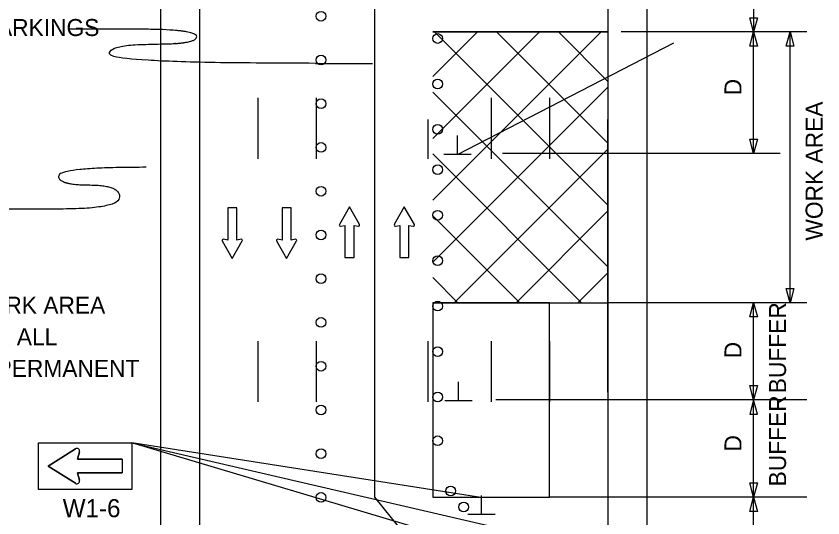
# Model space of a CAD drawing. Extents: x 16544 to 19504, y 5662 to 6922.
# Drawn here: x 16864 to 17195.9, y 6268.5 to 6474.9 of the extents above; entities that cross this region are included whole.
import ezdxf

# ---------------------------------------------------------------- set-up
doc = ezdxf.new("R2010")
doc.units = 0
for name, color, linetype in [('ALI_LEGAL_EX', 7, 'Continuous'), ('MT_SCRATCH_LEVEL_A', 7, 'Continuous'), ('MT_SCRATCH_LEVEL_E', 7, 'Continuous'), ('PAVT_EDGE_EX', 7, 'Continuous'), ('TRAFFIC_SIGNS_PR', 7, 'Continuous'), ('TYPICAL_TEXT_DIMEN_PR', 7, 'Continuous')]:
    doc.layers.add(name, color=color, linetype=linetype)

msp = doc.modelspace()

# ---------------------------------------------------------------- linework, layer by layer
at = {"layer": 'ALI_LEGAL_EX'}
for points in [[(16963.46, 6441.23), (16963.46, 6416.23)], [(16987.46, 6441.23), (16987.46, 6416.23)], [(16987.46, 6441.23), (16987.46, 6416.23)], [(17059.46, 6441.23), (17059.46, 6416.23)], [(17083.46, 6441.23), (17083.46, 6416.23)], [(17033.46, 6432.41), (17033.46, 6416.23)], [(17033.46, 6432.41), (17033.46, 6416.23)], [(17059.46, 6432.41), (17059.46, 6416.23)], [(16963.46, 6341.23), (16963.46, 6316.23)], [(16987.46, 6341.23), (16987.46, 6316.23)], [(16987.46, 6341.23), (16987.46, 6316.23)], [(17033.46, 6341.23), (17033.46, 6316.23)], [(17033.46, 6341.23), (17033.46, 6316.23)], [(17059.46, 6341.23), (17059.46, 6316.23)], [(17059.46, 6341.23), (17059.46, 6316.23)], [(17083.46, 6341.23), (17083.46, 6316.23)]]:
    msp.add_lwpolyline(points, dxfattribs=at)
at = {"layer": 'MT_SCRATCH_LEVEL_A'}
for p, q in [((17035.46, 6468.41), (17107.46, 6468.41)), ((17035.46, 6468.41), (17107.46, 6468.41)), ((17107.46, 6468.41), (17035.46, 6468.41)), ((17035.46, 6399.15), (17104.72, 6468.41)), ((17035.46, 6450.04), (17053.83, 6468.41)), ((17035.46, 6424.59), (17079.28, 6468.41)), ((17107.46, 6397.15), (17036.2, 6468.41)), ((17107.46, 6422.59), (17061.64, 6468.41)), ((17107.46, 6448.04), (17087.1, 6468.41)), ((17035.46, 6373.69), (17107.46, 6445.69)), ((17107.46, 6371.69), (17035.46, 6443.69)), ((17107.46, 6432.41), (17107.46, 6320.18)), ((17107.46, 6348.23), (17107.46, 6432.41)), ((17044.23, 6357.01), (17107.46, 6420.23)), ((17096.69, 6357.01), (17035.46, 6418.24)), ((17069.69, 6357.01), (17107.46, 6394.78)), ((17071.23, 6357.01), (17035.46, 6392.78)), ((17045.78, 6357.01), (17035.46, 6367.33)), ((17095.15, 6357.01), (17107.46, 6369.32)), ((17035.46, 6357.01), (17107.46, 6357.01)), ((17107.46, 6320.18), (17107.46, 6348.23))]:
    msp.add_line(p, q, dxfattribs=at)
at = {"layer": 'MT_SCRATCH_LEVEL_E'}
for p, q in [((16954.79, 6396.02), (16951.05, 6396.02)), ((16951.05, 6396.02), (16951.05, 6382.76)), ((16954.79, 6396.02), (16951.05, 6396.02)), ((16951.05, 6396.02), (16951.05, 6382.76)), ((16954.79, 6382.76), (16954.79, 6396.02)), ((16954.79, 6382.76), (16954.79, 6396.02)), ((16977.13, 6396.02), (16973.39, 6396.02)), ((16973.39, 6396.02), (16973.39, 6382.76)), ((16977.13, 6396.02), (16973.39, 6396.02)), ((16973.39, 6396.02), (16973.39, 6382.76)), ((16977.13, 6382.76), (16977.13, 6396.02)), ((16977.13, 6382.76), (16977.13, 6396.02)), ((17001.14, 6396.4), (16997.03, 6389.16)), ((17001.14, 6396.4), (16997.03, 6389.16)), ((17001.14, 6396.4), (16997.03, 6389.16)), ((17001.14, 6396.4), (16997.03, 6389.16)), ((17005.29, 6389.16), (17001.14, 6396.4)), ((17005.29, 6389.16), (17001.14, 6396.4)), ((17005.29, 6389.16), (17001.14, 6396.4)), ((17005.29, 6389.16), (17001.14, 6396.4)), ((17023.72, 6396.4), (17019.61, 6389.16)), ((17023.72, 6396.4), (17019.61, 6389.16)), ((17027.87, 6389.16), (17023.72, 6396.4)), ((17027.87, 6389.16), (17023.72, 6396.4)), ((16997.51, 6388.47), (16999.29, 6388.79)), ((16997.51, 6388.47), (16999.29, 6388.79)), ((16997.51, 6388.47), (16999.29, 6388.79)), ((16997.51, 6388.47), (16999.29, 6388.79)), ((16999.29, 6388.79), (16999.29, 6375.53)), ((16999.29, 6388.79), (16999.29, 6375.53)), ((16999.29, 6388.79), (16999.29, 6375.53)), ((16999.29, 6388.79), (16999.29, 6375.53)), ((17003.03, 6375.53), (17003.03, 6388.79)), ((17003.03, 6388.79), (17004.81, 6388.47)), ((17003.03, 6375.53), (17003.03, 6388.79)), ((17003.03, 6388.79), (17004.81, 6388.47)), ((17003.03, 6375.53), (17003.03, 6388.79)), ((17003.03, 6388.79), (17004.81, 6388.47)), ((17003.03, 6375.53), (17003.03, 6388.79)), ((17003.03, 6388.79), (17004.81, 6388.47)), ((17020.09, 6388.47), (17021.87, 6388.79)), ((17020.09, 6388.47), (17021.87, 6388.79)), ((17021.87, 6388.79), (17021.87, 6375.53)), ((17021.87, 6388.79), (17021.87, 6375.53)), ((17025.61, 6375.53), (17025.61, 6388.79)), ((17025.61, 6388.79), (17027.39, 6388.47)), ((17025.61, 6375.53), (17025.61, 6388.79)), ((17025.61, 6388.79), (17027.39, 6388.47)), ((16948.79, 6382.39), (16952.94, 6375.15)), ((16948.79, 6382.39), (16952.94, 6375.15)), ((16951.05, 6382.76), (16949.27, 6383.08)), ((16951.05, 6382.76), (16949.27, 6383.08)), ((16952.94, 6375.15), (16957.05, 6382.39)), ((16952.94, 6375.15), (16957.05, 6382.39)), ((16956.57, 6383.08), (16954.79, 6382.76)), ((16956.57, 6383.08), (16954.79, 6382.76)), ((16971.13, 6382.39), (16975.28, 6375.15)), ((16971.13, 6382.39), (16975.28, 6375.15)), ((16973.39, 6382.76), (16971.61, 6383.08)), ((16973.39, 6382.76), (16971.61, 6383.08)), ((16975.28, 6375.15), (16979.39, 6382.39)), ((16975.28, 6375.15), (16979.39, 6382.39)), ((16978.91, 6383.08), (16977.13, 6382.76)), ((16978.91, 6383.08), (16977.13, 6382.76)), ((16999.29, 6375.53), (17003.03, 6375.53)), ((16999.29, 6375.53), (17003.03, 6375.53)), ((16999.29, 6375.53), (17003.03, 6375.53)), ((16999.29, 6375.53), (17003.03, 6375.53)), ((17021.87, 6375.53), (17025.61, 6375.53)), ((17021.87, 6375.53), (17025.61, 6375.53))]:
    msp.add_line(p, q, dxfattribs=at)
for centre, start, end in [((16997.44, 6388.93), 150.4248, 279.9638), ((16997.44, 6388.93), 150.4248, 279.9638), ((16997.44, 6388.93), 150.4248, 279.9638), ((16997.44, 6388.93), 150.4248, 279.9638), ((17004.88, 6388.93), 260.0362, 29.7731), ((17004.88, 6388.93), 260.0362, 29.7731), ((17004.88, 6388.93), 260.0362, 29.7731), ((17004.88, 6388.93), 260.0362, 29.7731), ((17020.02, 6388.93), 150.4248, 279.9638), ((17020.02, 6388.93), 150.4248, 279.9638), ((17027.46, 6388.93), 260.0362, 29.7731), ((17027.46, 6388.93), 260.0362, 29.7731), ((16949.2, 6382.62), 80.0362, 209.7731), ((16949.2, 6382.62), 80.0362, 209.7731), ((16956.64, 6382.62), 330.4248, 99.9638), ((16956.64, 6382.62), 330.4248, 99.9638), ((16971.54, 6382.62), 80.0362, 209.7731), ((16971.54, 6382.62), 80.0362, 209.7731), ((16978.98, 6382.62), 330.4248, 99.9638), ((16978.98, 6382.62), 330.4248, 99.9638)]:
    msp.add_arc(centre, 0.463, start, end, dxfattribs=at)
at = {"layer": 'PAVT_EDGE_EX'}
for p, q in [((16923.46, 6880.02), (16923.46, 6074.05)), ((16939.46, 6880.02), (16939.46, 6074.05)), ((17107.46, 6880.02), (17107.46, 6074.05)), ((17123.46, 6880.02), (17123.46, 6074.05)), ((17011.46, 6478.73), (17011.46, 6277.01)), ((17011.46, 6277.01), (17059.46, 6217.4))]:
    msp.add_line(p, q, dxfattribs=at)
msp.add_lwpolyline([(17083.46, 6357.01), (17035.46, 6357.01), (17035.46, 6277.01), (17083.46, 6277.01)], close=True, dxfattribs=at)
at = {"layer": 'TRAFFIC_SIGNS_PR'}
for p, q in [((16888.38, 6296.88), (16877.22, 6289.78)), ((16889.23, 6292.58), (16890.06, 6295.64)), ((16907.62, 6292.58), (16889.23, 6292.58)), ((16907.62, 6292.58), (16907.62, 6286.98)), ((16877.22, 6289.78), (16888.38, 6282.68)), ((16890.06, 6283.92), (16889.23, 6286.98)), ((16889.23, 6286.98), (16907.62, 6286.98))]:
    msp.add_line(p, q, dxfattribs=at)
msp.add_lwpolyline([(16911.62, 6280.18), (16873.22, 6280.18), (16873.22, 6299.38), (16911.62, 6299.38)], close=True, dxfattribs=at)
for points in [[(16888.38, 6282.68), (16877.22, 6289.78), (16888.38, 6296.88)], [(16890.06, 6295.64), (16889.23, 6292.58), (16907.62, 6292.58), (16907.62, 6286.98), (16889.23, 6286.98), (16890.06, 6283.92)]]:
    msp.add_lwpolyline(points, dxfattribs=at)
for centre in [(16989.46, 6474.87), (17037.46, 6465.7), (16989.46, 6456.87), (17037.46, 6447), (16989.46, 6438.87), (17037.46, 6428.29), (16989.46, 6420.87), (17037.46, 6411.7), (16989.46, 6402.87), (17037.46, 6393), (16989.46, 6384.87), (17037.46, 6374.29), (16989.46, 6366.87), (17037.46, 6355.59), (16989.46, 6348.87), (17037.46, 6336.88), (16989.46, 6330.87), (17037.46, 6318.18), (16989.46, 6312.87), (17037.46, 6300.18), (16989.46, 6294.87), (17042.79, 6279.55), (16989.46, 6276.87), (17048.13, 6272.93)]:
    msp.add_circle(centre, 2, dxfattribs=at)
for centre, start, end in [((16888.99, 6295.94), 344.6731, 122.4696), ((16888.99, 6295.94), 344.6731, 122.4696), ((16888.99, 6283.62), 237.5304, 15.3269), ((16888.99, 6283.62), 237.5304, 15.3269)]:
    msp.add_arc(centre, 1.12, start, end, dxfattribs=at)
at = {"layer": 'TYPICAL_TEXT_DIMEN_PR'}
for p, q in [((17167.46, 6492.87), (17167.46, 6468.41)), ((17167.46, 6468.41), (17165.89, 6474.27)), ((17165.89, 6474.27), (17167.46, 6474.27)), ((17167.46, 6474.27), (17169.03, 6474.27)), ((17169.03, 6474.27), (17167.46, 6468.41)), ((17189.31, 6468.41), (17112.96, 6468.41)), ((17165.89, 6462.55), (17167.46, 6468.41)), ((17167.46, 6418.41), (17167.46, 6468.41)), ((17167.46, 6468.41), (17169.03, 6462.55)), ((17180.89, 6462.55), (17182.46, 6468.41)), ((17182.46, 6357.01), (17182.46, 6468.41)), ((17182.46, 6468.41), (17184.03, 6462.55)), ((17045.66, 6418.04), (17134.66, 6463.9)), ((17167.46, 6462.55), (17165.89, 6462.55)), ((17169.03, 6462.55), (17167.46, 6462.55)), ((17182.46, 6462.55), (17180.89, 6462.55)), ((17184.03, 6462.55), (17182.46, 6462.55)), ((16987.12, 6455.48), (17010.62, 6455.48)), ((17045.66, 6418.04), (17045.66, 6425.83)), ((17167.46, 6418.41), (17165.89, 6424.27)), ((17165.89, 6424.27), (17167.46, 6424.27)), ((17167.46, 6424.27), (17169.03, 6424.27)), ((17169.03, 6424.27), (17167.46, 6418.41)), ((17051.29, 6418.04), (17040.04, 6418.04)), ((17178.42, 6418.41), (17064.12, 6418.41)), ((17182.46, 6357.01), (17180.89, 6362.87)), ((17180.89, 6362.87), (17182.46, 6362.87)), ((17182.46, 6362.87), (17184.03, 6362.87)), ((17184.03, 6362.87), (17182.46, 6357.01)), ((17189.31, 6357.01), (17107.46, 6357.01)), ((17165.89, 6351.15), (17167.46, 6357.01)), ((17167.46, 6357.01), (17169.03, 6351.15)), ((17167.46, 6317.01), (17167.46, 6357.01)), ((17167.46, 6351.15), (17165.89, 6351.15)), ((17169.03, 6351.15), (17167.46, 6351.15)), ((17046.08, 6316.64), (17046.08, 6324.43)), ((17167.46, 6317.01), (17165.89, 6322.87)), ((17165.89, 6322.87), (17167.46, 6322.87)), ((17167.46, 6322.87), (17169.03, 6322.87)), ((17169.03, 6322.87), (17167.46, 6317.01)), ((17051.7, 6316.64), (17040.45, 6316.64)), ((17189.31, 6317.01), (17061.32, 6317.01)), ((17167.46, 6317.01), (17165.89, 6311.15)), ((17167.46, 6277.01), (17167.46, 6317.01)), ((17169.03, 6311.15), (17167.46, 6317.01)), ((17165.89, 6311.15), (17167.46, 6311.15)), ((17167.46, 6311.15), (17169.03, 6311.15)), ((17055.23, 6276.84), (16911.62, 6299.38)), ((16911.62, 6299.38), (17065.88, 6263.52)), ((17077.2, 6249.98), (16911.62, 6299.38)), ((17167.46, 6277.01), (17165.89, 6282.87)), ((17165.89, 6282.87), (17167.46, 6282.87)), ((17167.46, 6282.87), (17169.03, 6282.87)), ((17169.03, 6282.87), (17167.46, 6277.01)), ((17055.51, 6269.87), (17055.51, 6277.65)), ((17189.31, 6277.01), (17083.46, 6277.01)), ((17165.89, 6271.15), (17167.46, 6277.01)), ((17167.46, 6224.56), (17167.46, 6277.01)), ((17167.46, 6277.01), (17169.03, 6271.15)), ((17167.46, 6271.15), (17165.89, 6271.15)), ((17169.03, 6271.15), (17167.46, 6271.15)), ((17061.13, 6269.87), (17049.88, 6269.87))]:
    msp.add_line(p, q, dxfattribs=at)
for points in [[(16987.12, 6455.48), (16902.34, 6455.48), (16902.34, 6463.36), (16938.3, 6463.36), (16938.3, 6469.51), (16890.01, 6469.51), (16886.07, 6469.51)], [(16917.53, 6412.71), (16881.44, 6412.71), (16881.44, 6405.44), (16906.62, 6405.44), (16906.62, 6395.54), (16856.97, 6395.54), (16852.04, 6395.54)]]:
    msp.add_open_spline(points, degree=2, dxfattribs=at)

# ---------------------------------------------------------------- texts
at = {"layer": 'TRAFFIC_SIGNS_PR'}
for s, height, p in [('TEMPORARY PAVEMENT MARKINGS', 7, (16732.33, 6466.72)), ('PLACE THROUGHOUT WORK AREA', 7, (16740.48, 6352.48)), ('AS INDICATED AND AFTER ALL', 7, (16740.48, 6339.48)), ('MAJOR CROSSROADS IF PERMANENT', 7, (16740.48, 6326.48)), ('W1-6', 7.44, (16883.16, 6268.74))]:
    msp.add_text(s, height=height, dxfattribs=at).set_placement(p)
at = {"layer": 'TYPICAL_TEXT_DIMEN_PR'}
for s, p in [('D', (17162.46, 6442.33)), ('WORK AREA', (17195.85, 6382.55)), ('BUFFER', (17180.79, 6319.75)), ('D', (17162.46, 6334.11)), ('BUFFER', (17180.79, 6281.42)), ('D', (17162.46, 6295.78))]:
    msp.add_text(s, height=7, rotation=90, dxfattribs=at).set_placement(p)

doc.saveas('drawing.dxf')
